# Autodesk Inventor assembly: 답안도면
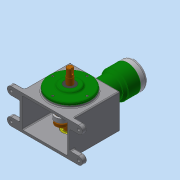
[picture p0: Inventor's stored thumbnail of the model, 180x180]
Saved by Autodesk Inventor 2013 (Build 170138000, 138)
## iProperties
Created: 2016-11
Part Number: 답안도면
Document SubType Name: Assembly
Designer: dgall
Mass: 5630.15 g
Surface Area: 4291.87 cm^2
Volume: 1587.82 cm^3
Density: 3.54584 g/cm^3
Author: dgall
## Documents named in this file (16)
- C:\Users\dgall\Desktop\361107V1012\답안조립품.iam
- C:\Users\dgall\Desktop\361107V1012\본체.ipt
- C:\Users\dgall\Desktop\361107V1012\베어링 20 x 47 x 14.ipt
- C:\Users\dgall\Desktop\361107V1012\메인크랭크축.ipt
- C:\Users\dgall\Desktop\361107V1012\베어링 NA 4902.ipt
- C:\Users\dgall\Desktop\361107V1012\크랭크보조축.ipt
- C:\Users\dgall\Desktop\361107V1012\앞커버.ipt
- C:\Users\dgall\Desktop\361107V1012\오일 실 20 35 8.ipt
- C:\Users\dgall\Desktop\361107V1012\실린더.ipt
- C:\Users\dgall\Desktop\361107V1012\피스톤.ipt
- C:\Users\dgall\Desktop\361107V1012\커넥팅로드.ipt
- C:\Users\dgall\Desktop\361107V1012\피스톤핀.ipt
- C:\Users\dgall\Desktop\361107V1012\실린더헤드.ipt
- C:\Users\dgall\Desktop\361107V1012\가변스프링.ipt
- C:\Users\dgall\Desktop\361107V1012\볼트 M4 x 8.ipt
- C:\Users\dgall\Desktop\361107V1012\볼트 M5 x 20.ipt
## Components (15 placed, 5 different names)
1. 피스톤:1
2. 피스톤핀:1
3. 가변스프링:1
4. ISO 4762 M5 x 20:1
5. ISO 4762 M5 x 20:2
6. ISO 4762 M5 x 20:3
7. ISO 4762 M5 x 20:4
8. ISO 4762 M4 x 8:1
9. ISO 4762 M4 x 8:2
10. ISO 4762 M4 x 8:3
11. ISO 4762 M4 x 8:4
12. ISO 4762 M4 x 8:5
13. ISO 4762 M4 x 8:6
14. ISO 4762 M4 x 8:7
15. ISO 4762 M4 x 8:8
